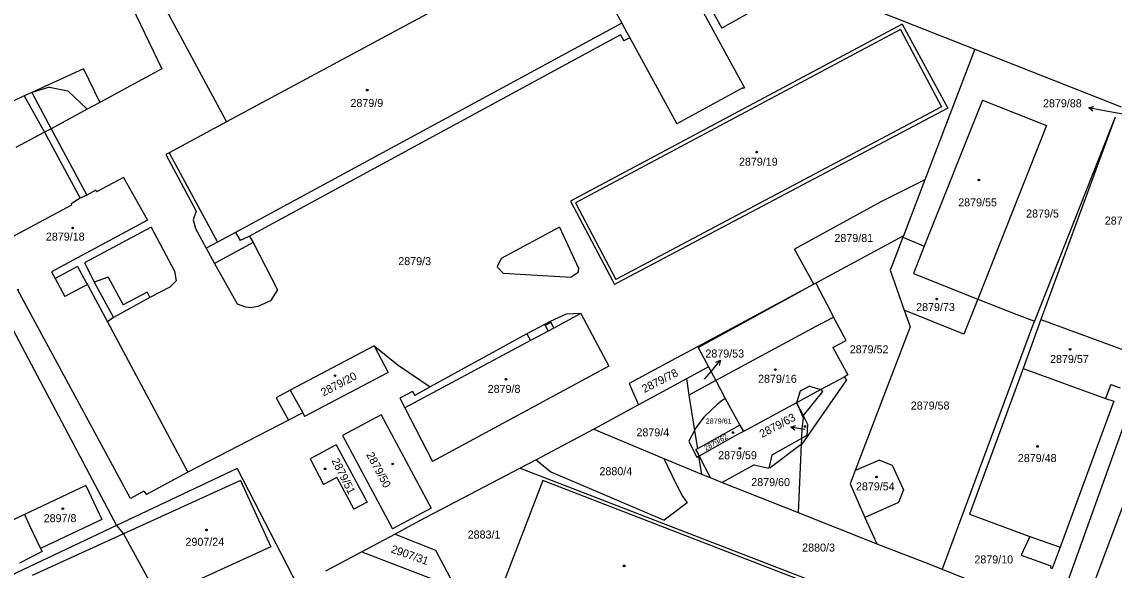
# Model space of a CAD drawing. Extents: x -593183 to -588034, y -1130415 to -1124994.
# Drawn here: x -591573.4 to -591341.4, y -1127983.9 to -1127867.5 of the extents above; entities that cross this region are included whole.
import ezdxf

# ---------------------------------------------------------------- set-up
doc = ezdxf.new("R2010")
doc.units = 0
for name, color, linetype in [('Vrstva 1', 7, 'Continuous'), ('Vrstva 16', 7, 'Continuous'), ('Vrstva 18', 7, 'Continuous'), ('Vrstva 19', 7, 'Continuous'), ('Vrstva 25', 7, 'Continuous'), ('Vrstva 4', 7, 'Continuous')]:
    doc.layers.add(name, color=color, linetype=linetype)

msp = doc.modelspace()

# ---------------------------------------------------------------- linework, layer by layer
at = {"layer": 'Vrstva 1'}
for p, q in [((-591465.9, -1127835.84), (-591371.05, -1127873.25)), ((-591437.67, -1127848.98), (-591419.96, -1127881.46)), ((-591432.36, -1127854.85), (-591424.77, -1127868.77)), ((-591553.18, -1127857.48), (-591543.64, -1127877.43)), ((-591545.96, -1127858.84), (-591529.89, -1127888.68)), ((-591476.69, -1127860.04), (-591529.89, -1127888.68)), ((-591419.42, -1127865.85), (-591424.77, -1127868.77)), ((-591386.78, -1127869.08), (-591455.83, -1127905.91)), ((-591386.78, -1127869.08), (-591378.08, -1127885.49)), ((-591446.23, -1127870.18), (-591525.04, -1127912.93)), ((-591446.23, -1127870.18), (-591445.51, -1127871.51)), ((-591444.27, -1127870.83), (-591445.51, -1127871.51)), ((-591444.27, -1127870.83), (-591434.32, -1127889.11)), ((-591371.05, -1127873.25), (-591381.64, -1127900.98)), ((-591371.05, -1127873.25), (-591339.94, -1127885.53)), ((-591543.64, -1127877.43), (-591551.96, -1127881.93)), ((-591551.96, -1127881.93), (-591556.83, -1127884.58)), ((-591420.26, -1127881.47), (-591434.32, -1127889.11)), ((-591420.26, -1127881.47), (-591420.2, -1127881.58)), ((-591419.96, -1127881.46), (-591420.2, -1127881.58)), ((-591556.83, -1127884.58), (-591559.47, -1127886)), ((-591378.08, -1127885.49), (-591447.24, -1127922.18)), ((-591369.41, -1127884.05), (-591381.75, -1127915.1)), ((-591369.41, -1127884.05), (-591355.78, -1127889.46)), ((-591559.47, -1127886), (-591567.14, -1127890.15)), ((-591341.26, -1127887.71), (-591358.37, -1127930.99)), ((-591341.26, -1127887.71), (-591356.98, -1127930.69)), ((-591567.14, -1127890.15), (-591568.57, -1127890.9)), ((-591529.89, -1127888.68), (-591542.09, -1127895.25)), ((-591355.78, -1127889.46), (-591370.42, -1127926.32)), ((-591568.57, -1127890.9), (-591574.65, -1127894.16)), ((-591318.29, -1127894.07), (-591353.86, -1127993.33)), ((-591542.09, -1127895.25), (-591531.82, -1127914.22)), ((-591551.74, -1127900.5), (-591557.5, -1127903.57)), ((-591551.74, -1127900.5), (-591546.68, -1127909.57)), ((-591381.64, -1127900.98), (-591391, -1127905.7)), ((-591381.64, -1127900.98), (-591386.2, -1127912.92)), ((-591557.68, -1127903.22), (-591559.55, -1127904.29)), ((-591557.68, -1127903.22), (-591557.5, -1127903.57)), ((-591562.82, -1127906.41), (-591579.17, -1127915.14)), ((-591560.94, -1127904.92), (-591562.91, -1127906.08)), ((-591562.91, -1127906.08), (-591562.82, -1127906.41)), ((-591559.55, -1127904.29), (-591560.94, -1127904.92)), ((-591455.83, -1127905.91), (-591447.24, -1127922.18)), ((-591391, -1127905.7), (-591409.32, -1127915.69)), ((-591546.68, -1127909.57), (-591567.04, -1127920.5)), ((-591527.96, -1127912.16), (-591531.82, -1127914.22)), ((-591527.96, -1127912.16), (-591527, -1127913.9)), ((-591525.31, -1127913.07), (-591527, -1127913.9)), ((-591525.04, -1127912.93), (-591525.31, -1127913.07)), ((-591386.2, -1127912.92), (-591404.79, -1127922.93)), ((-591386.3, -1127913.19), (-591388.57, -1127919.13)), ((-591386.2, -1127912.92), (-591386.3, -1127913.19)), ((-591386.3, -1127913.19), (-591381.75, -1127915.1)), ((-591317.66, -1127911.4), (-591350.8, -1128000.19)), ((-591405.23, -1127923.16), (-591409.32, -1127915.69)), ((-591381.75, -1127915.1), (-591384.06, -1127920.91)), ((-591388.57, -1127919.13), (-591388.98, -1127920.2)), ((-591388.98, -1127920.2), (-591386, -1127928.7)), ((-591567.04, -1127920.5), (-591566.27, -1127921.95)), ((-591566.27, -1127921.95), (-591564.24, -1127925.77)), ((-591384.06, -1127920.91), (-591370.42, -1127926.32)), ((-591559.41, -1127923.21), (-591564.24, -1127925.77)), ((-591559.41, -1127923.21), (-591559.26, -1127923.5)), ((-591559.26, -1127923.5), (-591555.15, -1127931.15)), ((-591407.69, -1127924.49), (-591429.87, -1127936.43)), ((-591429.78, -1127936.6), (-591407.69, -1127924.49)), ((-591405.23, -1127923.16), (-591407.69, -1127924.49)), ((-591404.79, -1127922.93), (-591405.23, -1127923.16)), ((-591404.79, -1127922.93), (-591402.47, -1127927.39)), ((-591579.21, -1127925.41), (-591553.24, -1127974.41)), ((-591402.47, -1127927.39), (-591401.04, -1127930.15)), ((-591370.42, -1127926.32), (-591373.37, -1127933.76)), ((-591370.42, -1127926.32), (-591362.1, -1127929.61)), ((-591457.76, -1127929.54), (-591461.17, -1127931.05)), ((-591454.65, -1127929.41), (-591457.76, -1127929.54)), ((-591454.65, -1127929.41), (-591448.7, -1127940.55)), ((-591386, -1127928.7), (-591384.77, -1127932.19)), ((-591373.37, -1127933.76), (-591386, -1127928.7)), ((-591362.1, -1127929.61), (-591358.37, -1127930.99)), ((-591555.15, -1127931.15), (-591538.12, -1127963.09)), ((-591462.39, -1127931.7), (-591466.11, -1127933.69)), ((-591461.17, -1127931.05), (-591462.39, -1127931.7)), ((-591398.37, -1127935.08), (-591401.04, -1127930.15)), ((-591358.78, -1127932.01), (-591377.94, -1127983.65)), ((-591356.98, -1127930.69), (-591360.76, -1127941.06)), ((-591358.37, -1127930.99), (-591358.78, -1127932.01)), ((-591356.98, -1127930.69), (-591339.47, -1127937.1)), ((-591466.11, -1127933.69), (-591486.63, -1127944.93)), ((-591384.77, -1127932.19), (-591396.42, -1127962.73)), ((-591498.54, -1127936.27), (-591516.37, -1127945.64)), ((-591498.54, -1127936.27), (-591495.61, -1127941.94)), ((-591429.87, -1127936.43), (-591434.56, -1127938.94)), ((-591429.78, -1127936.6), (-591427.55, -1127940.74)), ((-591401.16, -1127936.59), (-591398.37, -1127935.08)), ((-591401.16, -1127936.59), (-591398, -1127942.43)), ((-591434.56, -1127938.94), (-591444.41, -1127944.24)), ((-591448.7, -1127940.55), (-591486.19, -1127960.79)), ((-591427.55, -1127940.74), (-591432.27, -1127943.25)), ((-591427.55, -1127940.74), (-591426.01, -1127943.6)), ((-591360.76, -1127941.06), (-591372.13, -1127971.98)), ((-591360.76, -1127941.06), (-591343.26, -1127947.43)), ((-591495.61, -1127941.94), (-591513.34, -1127951.28)), ((-591432.27, -1127943.25), (-591442.42, -1127948.76)), ((-591432.27, -1127943.25), (-591431.73, -1127946.69)), ((-591426.01, -1127943.6), (-591431.73, -1127946.69)), ((-591426.01, -1127943.6), (-591424.05, -1127947.45)), ((-591398.74, -1127942.87), (-591403.73, -1127945.55)), ((-591398, -1127942.43), (-591398.74, -1127942.87)), ((-591516.37, -1127945.64), (-591519.34, -1127947.27)), ((-591490.41, -1127945.93), (-591493.11, -1127947.39)), ((-591490.41, -1127945.93), (-591489.94, -1127946.77)), ((-591486.63, -1127944.93), (-591489.94, -1127946.77)), ((-591444.41, -1127944.24), (-591442.42, -1127948.76)), ((-591403.73, -1127945.55), (-591403.35, -1127945.97)), ((-591342.18, -1127944.45), (-591343.26, -1127947.43)), ((-591342.18, -1127944.45), (-591340.18, -1127945.18)), ((-591519.34, -1127947.27), (-591516.71, -1127952.06)), ((-591493.11, -1127947.39), (-591492.05, -1127949.4)), ((-591431.73, -1127946.69), (-591430.55, -1127954.22)), ((-591424.05, -1127947.45), (-591420.92, -1127953.08)), ((-591403.35, -1127945.97), (-591407.44, -1127951.04)), ((-591341.51, -1127947.98), (-591352.91, -1127979.02)), ((-591343.26, -1127947.43), (-591341.51, -1127947.98)), ((-591513.7, -1127950.46), (-591516.71, -1127952.06)), ((-591513.7, -1127950.46), (-591513.34, -1127951.28)), ((-591492.05, -1127949.4), (-591486.19, -1127960.79)), ((-591442.42, -1127948.76), (-591451.9, -1127953.97)), ((-591408.92, -1127948.35), (-591420.17, -1127954.42)), ((-591408.92, -1127948.35), (-591408.31, -1127949.58)), ((-591408.92, -1127948.35), (-591407.51, -1127950.92)), ((-591408.31, -1127949.58), (-591407.58, -1127951.21)), ((-591497.06, -1127950.9), (-591505.26, -1127955.28)), ((-591497.06, -1127950.9), (-591486.48, -1127970.7)), ((-591407.46, -1127951.64), (-591407.73, -1127953.81)), ((-591407.58, -1127951.21), (-591407.46, -1127951.64)), ((-591407.51, -1127950.92), (-591407.44, -1127951.04)), ((-591407.44, -1127951.04), (-591406.58, -1127952.89)), ((-591406.58, -1127952.89), (-591406.67, -1127955.25)), ((-591451.9, -1127953.97), (-591464.17, -1127960.45)), ((-591451.9, -1127953.97), (-591437.04, -1127960.17)), ((-591430.55, -1127954.22), (-591429.94, -1127958.08)), ((-591420.92, -1127953.08), (-591429.94, -1127958.08)), ((-591421.42, -1127955.06), (-591429.52, -1127959.65)), ((-591420.17, -1127954.42), (-591421.42, -1127955.06)), ((-591420.92, -1127953.08), (-591420.17, -1127954.42)), ((-591407.73, -1127953.81), (-591407.82, -1127955.93)), ((-591506.6, -1127957.24), (-591512.17, -1127960.22)), ((-591506.6, -1127957.24), (-591500.06, -1127969.47)), ((-591505.26, -1127955.28), (-591494.68, -1127975.08)), ((-591407.82, -1127955.93), (-591414.1, -1127959.47)), ((-591407.88, -1127957.19), (-591408.54, -1127971.65)), ((-591407.82, -1127955.93), (-591407.88, -1127957.19)), ((-591406.67, -1127955.25), (-591407.82, -1127955.93)), ((-591429.94, -1127958.08), (-591430.34, -1127958.25)), ((-591430.34, -1127958.25), (-591429.77, -1127959.15)), ((-591429.77, -1127959.15), (-591429.68, -1127959.74)), ((-591429.52, -1127959.65), (-591429.68, -1127959.74)), ((-591429.68, -1127959.74), (-591429.09, -1127963.49)), ((-591414.1, -1127959.47), (-591414.74, -1127962.19)), ((-591512.17, -1127960.22), (-591509.29, -1127965.67)), ((-591464.17, -1127960.45), (-591467.59, -1127962.25)), ((-591464.17, -1127960.45), (-591461.06, -1127963)), ((-591437.04, -1127960.17), (-591429.09, -1127963.49)), ((-591437.04, -1127960.17), (-591434.4, -1127965.65)), ((-591417.89, -1127961.5), (-591424.69, -1127965.26)), ((-591417.89, -1127961.5), (-591414.74, -1127962.19)), ((-591391.27, -1127960.55), (-591396.42, -1127962.73)), ((-591391.27, -1127960.55), (-591388.54, -1127961.6)), ((-591388.54, -1127961.6), (-591386.17, -1127966.79)), ((-591527.67, -1127962.28), (-591553.24, -1127974.41)), ((-591538.12, -1127963.09), (-591546.87, -1127967.78)), ((-591527.67, -1127962.28), (-591514.76, -1127987.24)), ((-591506.47, -1127964.17), (-591509.29, -1127965.67)), ((-591506.47, -1127964.17), (-591502.84, -1127970.96)), ((-591467.59, -1127962.25), (-591488.92, -1127973.4)), ((-591467.59, -1127962.25), (-591362.61, -1128002.67)), ((-591461.06, -1127963), (-591436.96, -1127973.25)), ((-591429.09, -1127963.49), (-591427.19, -1127964.22)), ((-591427.19, -1127964.22), (-591424.69, -1127965.26)), ((-591396.42, -1127962.73), (-591397.49, -1127965.55)), ((-591559.78, -1127965.87), (-591572.8, -1127972.09)), ((-591559.78, -1127965.87), (-591556.34, -1127973.12)), ((-591526.96, -1127964.83), (-591551.76, -1127976.15)), ((-591526.96, -1127964.83), (-591520.52, -1127978.94)), ((-591462.75, -1127964.81), (-591472.01, -1127988.94)), ((-591434.4, -1127965.65), (-591433.07, -1127968.15)), ((-591424.69, -1127965.26), (-591408.54, -1127971.65)), ((-591397.49, -1127965.55), (-591394.37, -1127972.68)), ((-591386.17, -1127966.79), (-591387.25, -1127969.54)), ((-591547.45, -1127967.12), (-591546.87, -1127967.78)), ((-591433.07, -1127968.15), (-591432.11, -1127969.59)), ((-591500.06, -1127969.47), (-591502.84, -1127970.96)), ((-591486.48, -1127970.7), (-591494.68, -1127975.08)), ((-591432.11, -1127969.59), (-591436.96, -1127973.25)), ((-591387.25, -1127969.54), (-591394.37, -1127972.68)), ((-591572.8, -1127972.09), (-591578.95, -1127975.03)), ((-591556.34, -1127973.12), (-591569.36, -1127979.3)), ((-591488.92, -1127973.4), (-591494.09, -1127976.23)), ((-591408.54, -1127971.65), (-591391.81, -1127978.3)), ((-591394.37, -1127972.68), (-591391.81, -1127978.3)), ((-591372.13, -1127971.98), (-591359.37, -1127976.71)), ((-591553.24, -1127974.41), (-591673.98, -1128031.42)), ((-591553.24, -1127974.41), (-591551.76, -1127976.15)), ((-591551.76, -1127976.15), (-591571.16, -1127985)), ((-591551.76, -1127976.15), (-591544.34, -1127989.79)), ((-591494.09, -1127976.23), (-591501.18, -1127979.96)), ((-591494.09, -1127976.23), (-591485.52, -1127979.6)), ((-591391.81, -1127978.3), (-591381.68, -1127982.21)), ((-591359.37, -1127976.71), (-591361.19, -1127980.7)), ((-591569.04, -1127979.92), (-591573.85, -1127982.4)), ((-591569.36, -1127979.3), (-591569.04, -1127979.92)), ((-591520.52, -1127978.94), (-591544.34, -1127989.79)), ((-591501.18, -1127979.96), (-591508.9, -1127984.1)), ((-591501.18, -1127979.96), (-591481.32, -1127987.66)), ((-591485.52, -1127979.6), (-591481.32, -1127987.66)), ((-591361.19, -1127980.7), (-591354.87, -1127982.99)), ((-591352.91, -1127979.02), (-591354.57, -1127983.52)), ((-591381.68, -1127982.21), (-591377.94, -1127983.65)), ((-591354.87, -1127982.99), (-591354.99, -1127983.37)), ((-591377.94, -1127983.65), (-591353.86, -1127993.33)), ((-591354.99, -1127983.37), (-591354.57, -1127983.52))]:
    msp.add_line(p, q, dxfattribs=at)
for points in [[(-591547.45, -1127967.12), (-591550.31, -1127968.67), (-591574.25, -1127924.26), (-591573.97, -1127924.23)], [(-591364.24, -1128002.85), (-591411.69, -1127984.59), (-591462.75, -1127964.81)]]:
    msp.add_lwpolyline(points, dxfattribs=at)
at = {"layer": 'Vrstva 16'}
for p, q in [((-591339.57, -1127887.06), (-591343.89, -1127886.27)), ((-591428.44, -1127943.35), (-591426.95, -1127941.59)), ((-591407.13, -1127953.99), (-591407.16, -1127953.99))]:
    msp.add_line(p, q, dxfattribs=at)
at = {"layer": 'Vrstva 25'}
for p, q in [((-591343.89, -1127886.27), (-591346.84, -1127885.73)), ((-591426.95, -1127941.59), (-591425.01, -1127939.3)), ((-591407.16, -1127953.99), (-591410.12, -1127953.53))]:
    msp.add_line(p, q, dxfattribs=at)
for points in [[(-591345.95, -1127886.4), (-591346.84, -1127885.73), (-591345.77, -1127885.42)], [(-591426.04, -1127939.74), (-591425.01, -1127939.3), (-591425.28, -1127940.39)], [(-591409.21, -1127954.18), (-591410.12, -1127953.53), (-591409.06, -1127953.19)]]:
    msp.add_lwpolyline(points, dxfattribs=at)
for centre, radius in [((-591500.03, -1127881.95), 0.175), ((-591500.03, -1127881.95), 0.15), ((-591417.35, -1127895.1), 0.175), ((-591417.35, -1127895.1), 0.15), ((-591370.17, -1127901.02), 0.175), ((-591370.17, -1127901.02), 0.15), ((-591562.57, -1127911.23), 0.175), ((-591562.57, -1127911.23), 0.15), ((-591379.14, -1127926.3), 0.175), ((-591379.14, -1127926.3), 0.15), ((-591350.79, -1127937), 0.175), ((-591350.79, -1127937), 0.15), ((-591413.37, -1127941.29), 0.175), ((-591413.37, -1127941.29), 0.15), ((-591506.87, -1127942.58), 0.175), ((-591506.87, -1127942.58), 0.15), ((-591470.57, -1127943.34), 0.175), ((-591470.57, -1127943.34), 0.15), ((-591422.37, -1127954.66), 0.175), ((-591422.37, -1127954.66), 0.15), ((-591407.08, -1127953.37), 0.175), ((-591407.08, -1127953.37), 0.15), ((-591357.71, -1127957.61), 0.175), ((-591357.71, -1127957.61), 0.15), ((-591420.91, -1127958.01), 0.175), ((-591420.91, -1127958.01), 0.15), ((-591494.62, -1127961.32), 0.175), ((-591494.62, -1127961.32), 0.15), ((-591508.97, -1127962.36), 0.175), ((-591508.97, -1127962.36), 0.15), ((-591391.89, -1127964.09), 0.175), ((-591391.89, -1127964.09), 0.15), ((-591564.65, -1127970.83), 0.175), ((-591564.65, -1127970.83), 0.15), ((-591534.16, -1127975.32), 0.175), ((-591534.16, -1127975.32), 0.15), ((-591445.48, -1127982.96), 0.175), ((-591445.48, -1127982.96), 0.15)]:
    msp.add_circle(centre, radius, dxfattribs=at)
at = {"layer": 'Vrstva 4'}
for p, q in [((-591455.52, -1127850.24), (-591445.95, -1127867.74)), ((-591445.95, -1127867.74), (-591527.96, -1127912.16)), ((-591445.95, -1127867.74), (-591444.93, -1127869.7)), ((-591386.42, -1127867.94), (-591434.74, -1127893.69)), ((-591386.42, -1127867.94), (-591376.79, -1127885.76)), ((-591444.93, -1127869.7), (-591444.27, -1127870.83)), ((-591560.23, -1127877.46), (-591571.24, -1127882.43)), ((-591560.23, -1127877.46), (-591556.83, -1127884.58)), ((-591572.86, -1127883.13), (-591584.5, -1127888.89)), ((-591571.24, -1127882.43), (-591572.86, -1127883.13)), ((-591572.86, -1127883.13), (-591568.57, -1127890.9)), ((-591567.48, -1127881.31), (-591571.24, -1127882.43)), ((-591571.24, -1127882.43), (-591567.14, -1127890.15)), ((-591567.48, -1127881.31), (-591563.57, -1127882.12)), ((-591563.57, -1127882.12), (-591559.47, -1127886)), ((-591376.79, -1127885.76), (-591446.89, -1127922.85)), ((-591567.14, -1127890.15), (-591559.55, -1127904.29)), ((-591568.57, -1127890.9), (-591560.94, -1127904.92)), ((-591434.74, -1127893.69), (-591456.85, -1127905.54)), ((-591542.09, -1127895.25), (-591542.79, -1127895.63)), ((-591542.79, -1127895.63), (-591536.34, -1127907.65)), ((-591456.85, -1127905.54), (-591447.91, -1127922.53)), ((-591536.34, -1127907.65), (-591536.99, -1127909.51)), ((-591545.91, -1127911.07), (-591560.05, -1127918.64)), ((-591545.91, -1127911.07), (-591540.92, -1127920.4)), ((-591536.99, -1127909.51), (-591536.49, -1127911.32)), ((-591459.23, -1127911.08), (-591471.59, -1127917.69)), ((-591459.23, -1127911.08), (-591455.16, -1127919.75)), ((-591536.49, -1127911.32), (-591534.24, -1127915.54)), ((-591525.04, -1127912.93), (-591524.27, -1127914.28)), ((-591531.82, -1127914.22), (-591534.24, -1127915.54)), ((-591534.24, -1127915.54), (-591532.47, -1127918.76)), ((-591524.27, -1127914.28), (-591532.47, -1127918.76)), ((-591524.27, -1127914.28), (-591519.06, -1127924.35)), ((-591471.59, -1127917.69), (-591472.44, -1127919.5)), ((-591561.51, -1127919.41), (-591566.27, -1127921.95)), ((-591561.51, -1127919.41), (-591559.6, -1127922.95)), ((-591560.05, -1127918.64), (-591558.2, -1127922.21)), ((-591540.92, -1127920.4), (-591540.61, -1127922.44)), ((-591532.47, -1127918.76), (-591527.63, -1127927.34)), ((-591472.44, -1127919.5), (-591471.14, -1127920.82)), ((-591455.16, -1127919.75), (-591455.34, -1127920.78)), ((-591558.2, -1127922.21), (-591557.98, -1127922.73)), ((-591555.06, -1127921.7), (-591557.98, -1127922.73)), ((-591557.98, -1127922.73), (-591553.91, -1127930.22)), ((-591555.06, -1127921.7), (-591551.81, -1127927.55)), ((-591540.61, -1127922.44), (-591541.92, -1127923.82)), ((-591471.14, -1127920.82), (-591456.72, -1127921.66)), ((-591455.34, -1127920.78), (-591456.72, -1127921.66)), ((-591447.91, -1127922.53), (-591447.56, -1127923.2)), ((-591559.6, -1127922.95), (-591559.41, -1127923.21)), ((-591546.77, -1127924.82), (-591551.81, -1127927.55)), ((-591546.77, -1127924.82), (-591546.18, -1127925.95)), ((-591541.92, -1127923.82), (-591546.18, -1127925.95)), ((-591519.06, -1127924.35), (-591520.59, -1127926.7)), ((-591446.89, -1127922.85), (-591447.56, -1127923.2)), ((-591546.18, -1127925.95), (-591553.91, -1127930.22)), ((-591527.63, -1127927.34), (-591525.84, -1127927.93)), ((-591520.59, -1127926.7), (-591523.25, -1127927.88)), ((-591525.84, -1127927.93), (-591524.44, -1127928.09)), ((-591523.25, -1127927.88), (-591524.44, -1127928.09)), ((-591454.65, -1127929.41), (-591460.4, -1127932.48)), ((-591553.91, -1127930.22), (-591555.15, -1127931.15)), ((-591462.39, -1127931.7), (-591462.27, -1127931.92)), ((-591461.06, -1127931.27), (-591462.27, -1127931.92)), ((-591462.27, -1127931.92), (-591461.62, -1127933.13)), ((-591461.17, -1127931.05), (-591461.06, -1127931.27)), ((-591461.06, -1127931.27), (-591460.4, -1127932.48)), ((-591403.83, -1127931.66), (-591426.01, -1127943.6)), ((-591403.83, -1127931.66), (-591401.04, -1127930.15)), ((-591466.11, -1127933.69), (-591465.34, -1127935.12)), ((-591461.62, -1127933.13), (-591465.34, -1127935.12)), ((-591460.4, -1127932.48), (-591461.62, -1127933.13)), ((-591498.54, -1127936.27), (-591493.46, -1127940.33)), ((-591465.34, -1127935.12), (-591492.05, -1127949.4)), ((-591493.46, -1127940.33), (-591486.63, -1127944.93)), ((-591398.27, -1127943.5), (-591407.78, -1127957.11)), ((-591398.74, -1127942.87), (-591398.27, -1127943.5)), ((-591516.37, -1127945.64), (-591513.7, -1127950.46)), ((-591403.73, -1127945.55), (-591408.92, -1127948.35)), ((-591408.12, -1127945.84), (-591408.92, -1127948.35)), ((-591406.1, -1127944.79), (-591408.12, -1127945.84)), ((-591406.1, -1127944.79), (-591403.73, -1127945.55)), ((-591424.98, -1127948.09), (-591425.77, -1127948.77)), ((-591424.05, -1127947.45), (-591424.98, -1127948.09)), ((-591425.77, -1127948.77), (-591428.47, -1127951.35)), ((-591516.71, -1127952.06), (-591538.12, -1127963.09)), ((-591428.47, -1127951.35), (-591430.26, -1127953.66)), ((-591430.55, -1127954.22), (-591431.74, -1127956.52)), ((-591430.26, -1127953.66), (-591430.55, -1127954.22)), ((-591431.74, -1127956.52), (-591430.06, -1127959.96)), ((-591407.88, -1127957.19), (-591414.45, -1127962.13)), ((-591407.78, -1127957.11), (-591407.88, -1127957.19)), ((-591429.68, -1127959.74), (-591430.06, -1127959.96)), ((-591429.77, -1127959.15), (-591429.52, -1127959.65)), ((-591429.52, -1127959.65), (-591427.19, -1127964.22)), ((-591414.45, -1127962.13), (-591414.74, -1127962.19)), ((-591572.8, -1127972.09), (-591571.7, -1127974.39)), ((-591571.7, -1127974.39), (-591569.36, -1127979.3)), ((-591359.37, -1127976.71), (-591352.91, -1127979.02))]:
    msp.add_line(p, q, dxfattribs=at)

# ---------------------------------------------------------------- texts
at = {"layer": 'Vrstva 16'}
for s, p in [('2879/88', (-591356.55, -1127885.59)), ('2879/53', (-591428.23, -1127938.73))]:
    msp.add_text(s, height=1.7, dxfattribs=at).set_placement(p)
msp.add_text('2879/63', height=1.7, rotation=27.8611, dxfattribs=at).set_placement((-591416.18, -1127955.81))
at = {"layer": 'Vrstva 18'}
for s, height, p in [('2879/5', 1.7, (-591360.13, -1127909)), ('2879/81', 1.7, (-591400.83, -1127914.2)), ('2879/3', 1.7, (-591493.43, -1127919.11)), ('2879/52', 1.7, (-591397.58, -1127937.84)), ('2879/53', 0.1, (-591428.7, -1127943.35)), ('2879/58', 1.7, (-591384.62, -1127949.77)), ('2879/61', 1.1, (-591428.15, -1127952.78)), ('2879/4', 1.7, (-591442.87, -1127955.46)), ('2880/4', 1.7, (-591450.72, -1127963.71)), ('2879/60', 1.7, (-591418.49, -1127966.03)), ('2883/1', 1.7, (-591478.7, -1127977.16)), ('2880/3', 1.7, (-591407.68, -1127979.93)), ('2879/10', 1.7, (-591371.12, -1127982.45))]:
    msp.add_text(s, height=height, dxfattribs=at).set_placement(p)
for s, rotation, p in [('2879/78', 27.1213, (-591441.16, -1127946.27)), ('2907/31', 340.594, (-591495.12, -1127980.08))]:
    msp.add_text(s, height=1.7, rotation=rotation, dxfattribs=at).set_placement(p)
at = {"layer": 'Vrstva 19'}
for s, height, p in [('2879/9', 1.7, (-591503.59, -1127885.53)), ('2879/19', 1.7, (-591421.1, -1127898)), ('2879/55', 1.7, (-591374.55, -1127906.63)), ('2879/56', 1.7, (-591343.43, -1127910.5)), ('2879/18', 1.7, (-591568.25, -1127913.91)), ('2879/73', 1.7, (-591383.48, -1127928.86)), ('2879/57', 1.7, (-591355.05, -1127939.89)), ('2879/16', 1.7, (-591417.05, -1127944.09)), ('2879/8', 1.7, (-591474.45, -1127946.24)), ('2879/63', 0.1, (-591407.39, -1127953.99)), ('2879/59', 1.7, (-591425.52, -1127960.32)), ('2879/48', 1.7, (-591361.89, -1127960.92)), ('2879/54', 1.7, (-591396.26, -1127966.94)), ('2897/8', 1.7, (-591568.72, -1127973.69)), ('2907/24', 1.7, (-591538.61, -1127978.71))]:
    msp.add_text(s, height=height, dxfattribs=at).set_placement(p)
for s, height, rotation, p in [('2879/20', 1.7, 27.7798, (-591509.33, -1127947.03)), ('2879/62', 1.1, 29.5388, (-591428.13, -1127958.57)), ('2879/50', 1.7, 298.3391, (-591500.29, -1127959.35)), ('2879/51', 1.7, 296.8008, (-591507.66, -1127960.61))]:
    msp.add_text(s, height=height, rotation=rotation, dxfattribs=at).set_placement(p)

doc.saveas('drawing.dxf')
